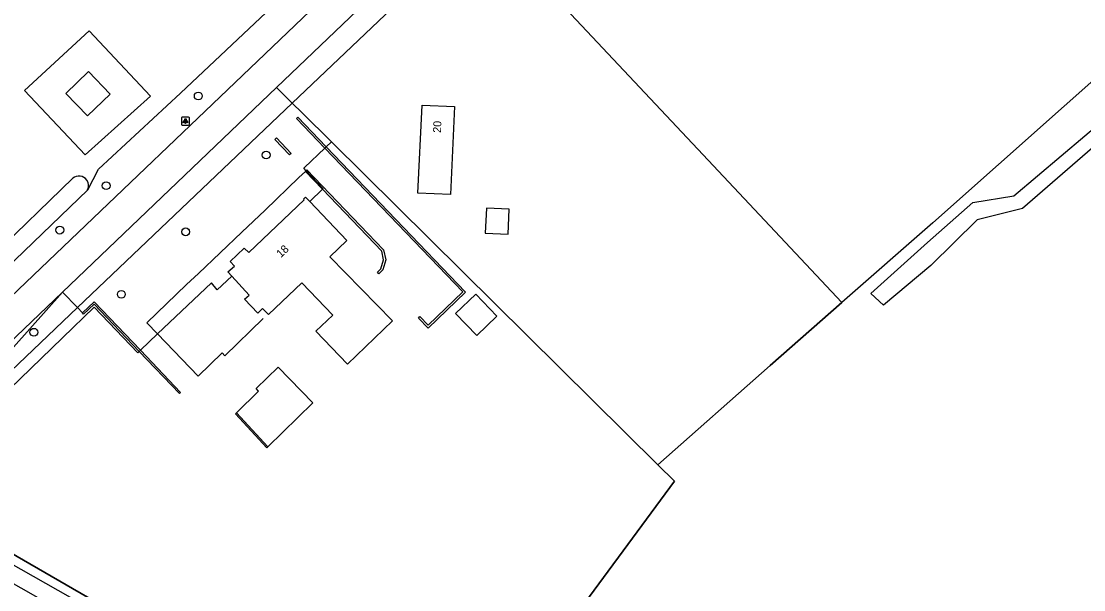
# Model space of a CAD drawing. Extents: x 157154 to 159278, y 385000 to 386650.
# Drawn here: x 157460.3 to 157593.2, y 385928.5 to 385999.6 of the extents above; entities that cross this region are included whole.
import ezdxf

# ---------------------------------------------------------------- set-up
doc = ezdxf.new("R2010")
doc.units = 0
for name, color, linetype in [('IMGEO_Boom', 7, 'Continuous'), ('IMGEO_Gemengd_bos', 7, 'Continuous'), ('IMGEO_Grasland_overig', 7, 'Continuous'), ('IMGEO_Groenvoorziening', 7, 'Continuous'), ('IMGEO_Hek', 7, 'Continuous'), ('IMGEO_Lichtpunt', 7, 'Continuous'), ('IMGEO_Loofbos', 7, 'Continuous'), ('IMGEO_Muur', 7, 'Continuous'), ('IMGEO_Pand', 7, 'Continuous'), ('IMGEO_Pand_nummerreeks', 7, 'Continuous'), ('IMGEO_Rijbaan_lokaal_halfverhard', 7, 'Continuous'), ('IMGEO_Rijbaan_lokaal_open', 7, 'Continuous'), ('IMGEO_Waterloop', 7, 'Continuous')]:
    doc.layers.add(name, color=color, linetype=linetype)

msp = doc.modelspace()

# ---------------------------------------------------------------- linework, layer by layer
at = {"layer": 'IMGEO_Boom'}
for centre in [(157482.47, 385990.23), (157490.95, 385982.84), (157470.95, 385979), (157465.16, 385973.45), (157480.89, 385973.23), (157472.85, 385965.42), (157461.92, 385960.67)]:
    msp.add_circle(centre, 0.489, dxfattribs=at)
at = {"layer": 'IMGEO_Gemengd_bos'}
for points in [[(157543.9, 386034.12), (157544.83, 386033.82), (157546.23, 386033.37), (157552.49, 386039.41), (157574.16, 386060.33), (157597.82, 386083.26), (157600.88, 386083.37), (157618.6, 386072.25), (157588.24, 386039.03), (157590.26, 386031.28), (157597.98, 386000), (157598.9, 385996.27), (157574.27, 385974.36), (157562.9, 385964.41)], [(157467.36, 385963.75), (157443.32, 385940.84)], [(157539.91, 385944.1), (157541.98, 385942.04), (157512.6, 385902.07), (157445.67, 385940.77), (157469.45, 385963.81), (157474.9, 385958.09), (157475.08, 385958.27), (157469.44, 385964.19), (157468.14, 385962.94), (157468, 385963.08), (157467.36, 385963.75)], [(157539.91, 385944.1), (157553.95, 385956.53), (157562.9, 385964.41)]]:
    msp.add_lwpolyline(points, dxfattribs=at)
at = {"layer": 'IMGEO_Grasland_overig'}
for points in [[(157562.9, 385964.41), (157544.9, 385983.59), (157521.13, 386008.94), (157538.17, 386025.6), (157537.63, 386027.64)], [(157516.62, 386010.7), (157494.21, 385989.34)], [(157494.21, 385989.34), (157495.44, 385988.12), (157499.11, 385984.49), (157539.91, 385944.1)]]:
    msp.add_lwpolyline(points, dxfattribs=at)
at = {"layer": 'IMGEO_Groenvoorziening'}
msp.add_lwpolyline([(157443.32, 385940.84), (157465.49, 385965.68)], dxfattribs=at)
at = {"layer": 'IMGEO_Hek'}
for points in [[(157543.9, 386034.12), (157544.83, 386033.82), (157546.23, 386033.37), (157552.49, 386039.41), (157574.16, 386060.33), (157597.82, 386083.26), (157600.88, 386083.37), (157618.6, 386072.25), (157588.24, 386039.03), (157590.26, 386031.28), (157597.98, 386000), (157598.9, 385996.27), (157574.27, 385974.36), (157562.9, 385964.41)], [(157521.13, 386008.94), (157544.9, 385983.59), (157562.9, 385964.41)], [(157468.33, 385982.85), (157460.77, 385990.93), (157468.85, 385998.39), (157476.48, 385990.21), (157468.33, 385982.85)], [(157495.44, 385988.12), (157499.11, 385984.49)], [(157498.47, 385983.88), (157499.11, 385984.49)], [(157539.91, 385944.1), (157499.11, 385984.49)], [(157495.76, 385981.29), (157498.29, 385983.71)], [(157498.29, 385983.71), (157498.47, 385983.88)], [(157495.96, 385980.88), (157495.66, 385981.2), (157495.76, 385981.29)], [(157498.01, 385978.56), (157498.09, 385978.63), (157495.96, 385980.88)], [(157496.4, 385977.02), (157498.01, 385978.56)], [(157486.65, 385967.67), (157484.83, 385965.96), (157484.12, 385966.86), (157477.39, 385960.46)], [(157475.08, 385958.27), (157474.9, 385958.09), (157469.45, 385963.81), (157445.67, 385940.77), (157512.6, 385902.07), (157541.98, 385942.04), (157539.91, 385944.1)], [(157562.9, 385964.41), (157553.95, 385956.53), (157539.91, 385944.1)], [(157477.39, 385960.46), (157475.23, 385958.41)], [(157475.23, 385958.41), (157475.08, 385958.27)]]:
    msp.add_lwpolyline(points, dxfattribs=at)
at = {"layer": 'IMGEO_Lichtpunt'}
for p, q in [((157480.37, 385987.49), (157480.37, 385986.69)), ((157480.37, 385987.49), (157480.37, 385986.69)), ((157481.27, 385987.59), (157480.46, 385987.59)), ((157481.27, 385987.59), (157480.46, 385987.59)), ((157481.37, 385986.69), (157481.37, 385987.49)), ((157481.37, 385986.69), (157481.37, 385987.49)), ((157480.46, 385986.59), (157481.27, 385986.59)), ((157480.46, 385986.59), (157481.27, 385986.59))]:
    msp.add_line(p, q, dxfattribs=at)
for points in [[(157480.74, 385987.16), (157480.78, 385987.13), (157480.6, 385986.87), (157480.56, 385986.89), (157480.74, 385987.16)], [(157480.85, 385987.11), (157480.89, 385987.11), (157480.89, 385986.79), (157480.85, 385986.79), (157480.85, 385987.11)], [(157480.96, 385987.13), (157480.99, 385987.16), (157481.18, 385986.89), (157481.14, 385986.87), (157480.96, 385987.13)]]:
    msp.add_lwpolyline(points, dxfattribs=at)
msp.add_circle((157480.87, 385987.29), 0.0994, dxfattribs=at)
for centre, start, end in [((157480.46, 385987.49), 90, 180), ((157480.46, 385987.49), 90, 180), ((157481.27, 385987.49), 0, 90), ((157481.27, 385987.49), 0, 90), ((157480.46, 385986.69), 180, 270), ((157480.46, 385986.69), 180, 270), ((157481.27, 385986.69), 270, 0), ((157481.27, 385986.69), 270, 360)]:
    msp.add_arc(centre, 0.0946, start, end, dxfattribs=at)
at = {"layer": 'IMGEO_Loofbos'}
for points in [[(157468.65, 385978.5), (157470, 385981.06), (157480.25, 385990.59), (157514.49, 386022.88)], [(157476.48, 385990.21), (157468.33, 385982.85), (157460.77, 385990.93), (157468.85, 385998.39), (157476.48, 385990.21)]]:
    msp.add_lwpolyline(points, dxfattribs=at)
at = {"layer": 'IMGEO_Muur'}
for points in [[(157494.74, 385987.4), (157494.93, 385987.57)], [(157498.29, 385983.71), (157494.74, 385987.4)], [(157494.93, 385987.57), (157498.47, 385983.88)], [(157492.05, 385984.79), (157492.23, 385984.98)], [(157493.89, 385982.87), (157492.05, 385984.79)], [(157492.23, 385984.98), (157494.08, 385983.05)], [(157494.08, 385983.05), (157493.89, 385982.87)], [(157510.18, 385962.63), (157511.22, 385961.54), (157515.53, 385965.71), (157498.29, 385983.71)], [(157498.47, 385983.88), (157515.88, 385965.7), (157511.22, 385961.18), (157509.99, 385962.45), (157510.18, 385962.63)], [(157495.87, 385980.8), (157495.05, 385980.01)], [(157495.87, 385980.8), (157495.96, 385980.88)], [(157498.01, 385978.56), (157495.87, 385980.8)], [(157495.96, 385980.88), (157496.06, 385980.98)], [(157496.06, 385980.98), (157505.61, 385970.99), (157505.9, 385969.72), (157505.53, 385968.46), (157505.04, 385967.99)], [(157495.05, 385980.01), (157490.83, 385975.96)], [(157505.04, 385967.99), (157504.87, 385968.17), (157505.3, 385968.59), (157505.62, 385969.71), (157505.41, 385970.83), (157498.01, 385978.56)], [(157490.83, 385975.96), (157487.91, 385973.19)], [(157487.91, 385973.19), (157482.49, 385968.01)], [(157482.49, 385968.01), (157481.01, 385966.64)], [(157481.01, 385966.64), (157476.04, 385961.86)], [(157468, 385963.08), (157469.46, 385964.47), (157475.23, 385958.41)], [(157475.08, 385958.27), (157469.44, 385964.19), (157468.14, 385962.94), (157468, 385963.08)], [(157476.04, 385961.86), (157477.39, 385960.46)], [(157477.39, 385960.46), (157482.44, 385955.19), (157485.45, 385958.08), (157485.77, 385957.73), (157490.58, 385962.39)], [(157475.23, 385958.41), (157480.26, 385953.13), (157480.12, 385952.99), (157475.08, 385958.27)], [(157487.26, 385950.6), (157490, 385953.29), (157489.7, 385953.63), (157492.47, 385956.31), (157496.8, 385951.82), (157491.17, 385946.34)], [(157487.26, 385950.6), (157487.12, 385950.46), (157491.02, 385946.21), (157491.17, 385946.34)], [(157491.17, 385946.34), (157487.26, 385950.6)]]:
    msp.add_lwpolyline(points, dxfattribs=at)
at = {"layer": 'IMGEO_Pand'}
for points in [[(157468.62, 385987.74), (157471.47, 385990.47), (157468.77, 385993.28), (157465.92, 385990.54), (157468.62, 385987.74)], [(157513.98, 385977.89), (157509.93, 385978.08), (157510.46, 385989.08), (157514.51, 385988.9), (157513.98, 385977.89)], [(157497.18, 385960.79), (157499.28, 385962.8), (157495.4, 385966.85), (157491.24, 385962.87), (157490.51, 385963.62), (157489.93, 385963.06), (157488.26, 385964.81), (157488.83, 385965.31), (157486.65, 385967.67), (157486.15, 385968.22), (157487.01, 385968.92), (157486.45, 385969.51), (157488.2, 385971.19), (157488.77, 385970.63), (157495.71, 385977.25), (157495.64, 385977.33), (157495.89, 385977.56), (157496.4, 385977.02), (157501.03, 385972.15), (157498.93, 385970.12), (157506.73, 385962.08), (157501.11, 385956.69), (157497.18, 385960.79)], [(157518.48, 385976.21), (157518.35, 385973.06), (157521.2, 385972.92), (157521.35, 385976.08), (157518.48, 385976.21)], [(157514.63, 385963), (157517.27, 385960.25), (157519.8, 385962.67), (157517.15, 385965.42), (157514.63, 385963)]]:
    msp.add_lwpolyline(points, dxfattribs=at)
at = {"layer": 'IMGEO_Rijbaan_lokaal_halfverhard'}
for points in [[(157494.21, 385989.34), (157492.25, 385991.28)], [(157494.21, 385989.34), (157467.36, 385963.75)], [(157465.49, 385965.68), (157467.36, 385963.75)]]:
    msp.add_lwpolyline(points, dxfattribs=at)
at = {"layer": 'IMGEO_Rijbaan_lokaal_open'}
for points in [[(157492.25, 385991.28), (157534.38, 386031.56)], [(157516.04, 386019.65), (157438.46, 385945.46), (157436.42, 385943.53), (157433.81, 385941.48), (157433.37, 385941.16)], [(157465.49, 385965.68), (157492.25, 385991.28)], [(157465.49, 385965.68), (157441.44, 385942.69)]]:
    msp.add_lwpolyline(points, dxfattribs=at)
at = {"layer": 'IMGEO_Waterloop'}
for points in [[(157603.3, 385991.6), (157585.49, 385976.16), (157579.81, 385974.73), (157574.04, 385969), (157568.14, 385964.06), (157566.54, 385965.53), (157573.64, 385971.91), (157579.3, 385976.92), (157584.41, 385977.74), (157602.17, 385992.74)], [(157456.7, 385970.18), (157466.79, 385979.94)], [(157458.36, 385968.55), (157458.4, 385968.59), (157458.43, 385968.62), (157468.65, 385978.5)], [(157444.27, 385940.14), (157500, 385908.46), (157548.85, 385880.7), (157597.28, 385853.18), (157604.81, 385848.82)], [(157603.52, 385846.95), (157547.72, 385878.78), (157500, 385906), (157443.12, 385938.45)]]:
    msp.add_lwpolyline(points, dxfattribs=at)
for start, end in [(35.0054, 130.2569), (334.1783, 35.0597)]:
    msp.add_arc((157467.56, 385979.02), 1.2, start, end, dxfattribs=at)

# ---------------------------------------------------------------- texts
at = {"layer": 'IMGEO_Pand_nummerreeks'}
for s, rotation, p in [('20', 87.2386, (157512.8, 385985.6)), ('18', 43.6846, (157492.8, 385969.94))]:
    msp.add_text(s, height=1, rotation=rotation, dxfattribs=at).set_placement(p)

doc.saveas('drawing.dxf')
